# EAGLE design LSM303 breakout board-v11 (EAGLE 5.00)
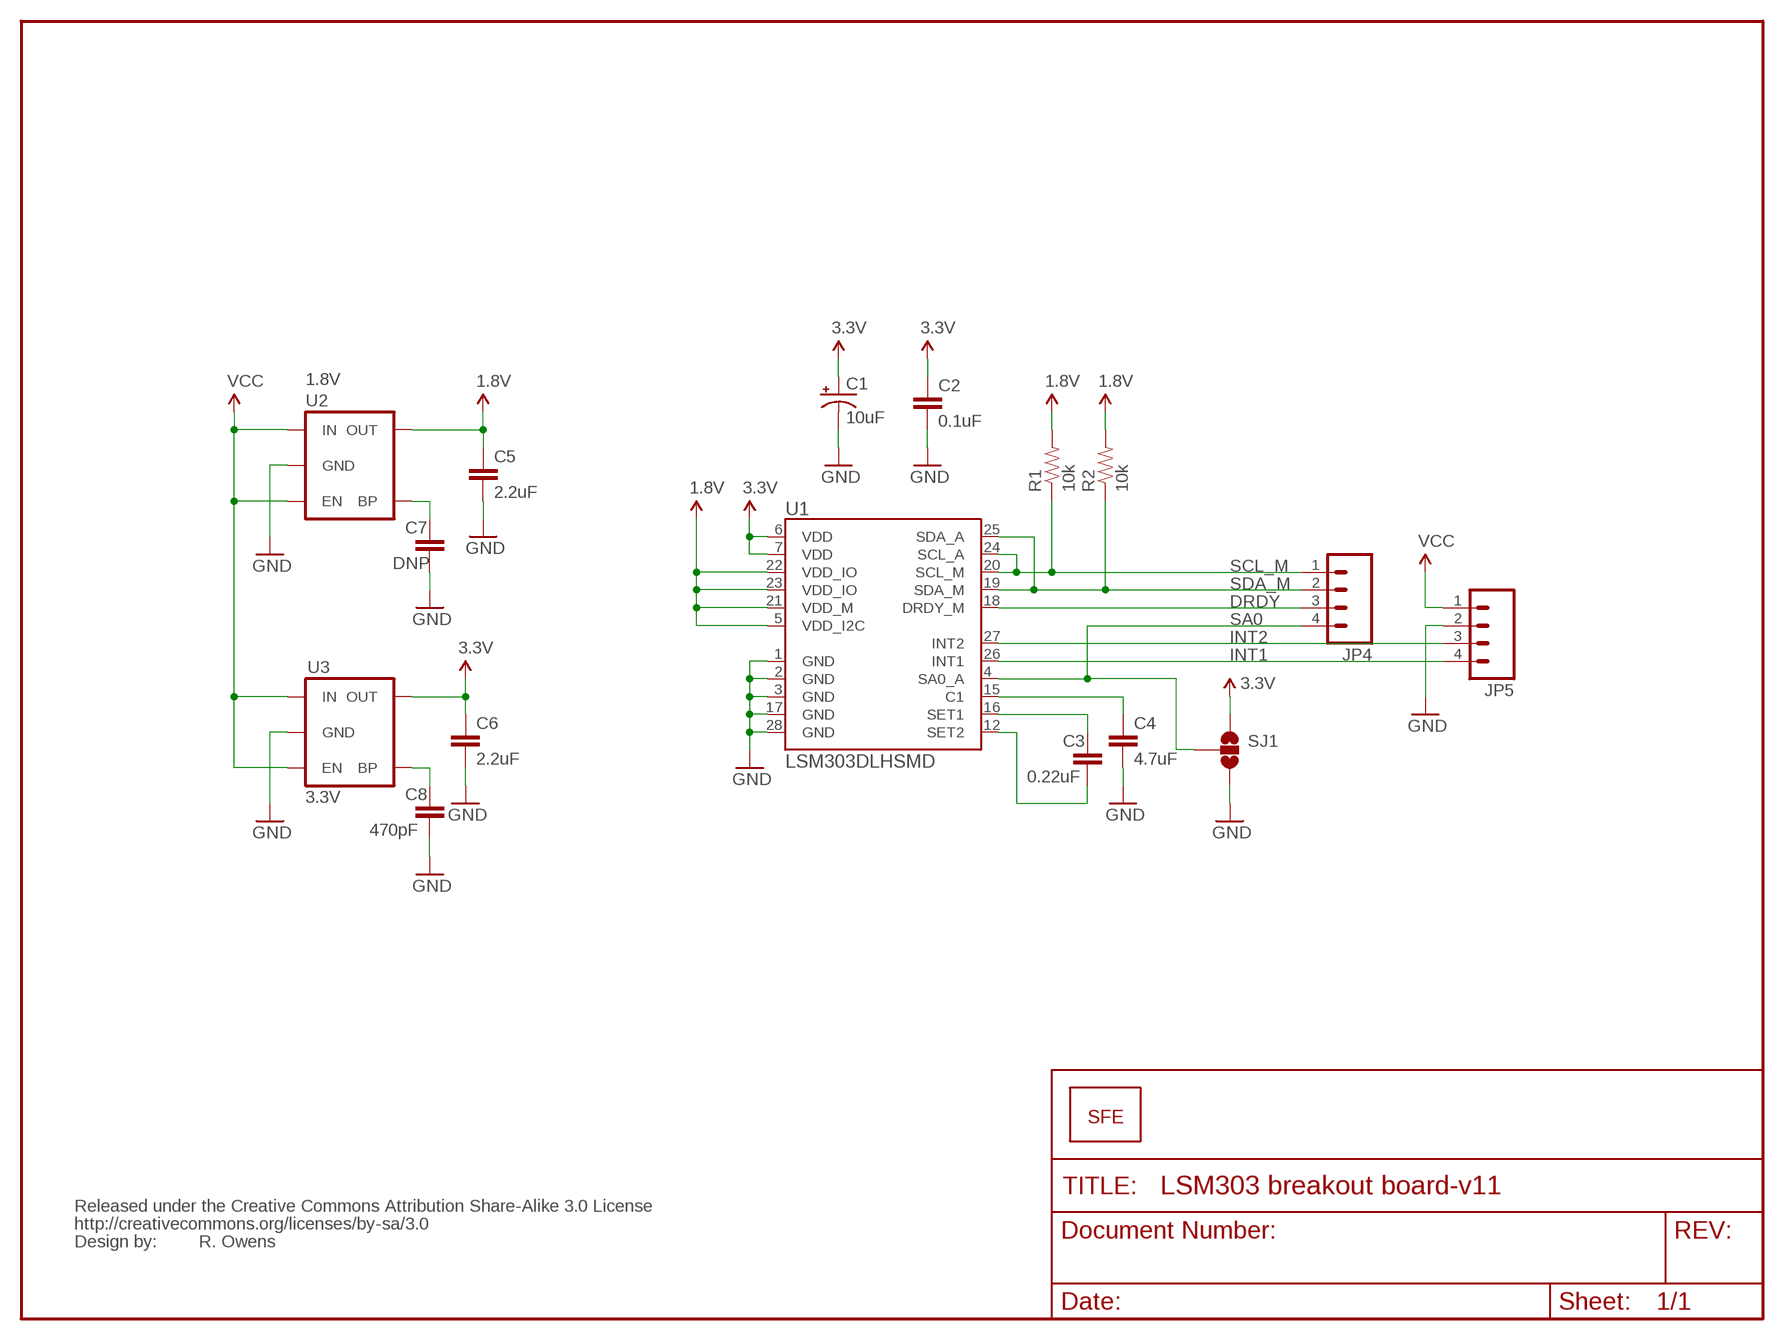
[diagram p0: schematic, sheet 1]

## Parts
C1  10uF  CAP_POL1206  [EIA3216]
C2  0.1uF  CAP0603-CAP  [0603-CAP]
C3  0.22uF  CAP0603-CAP  [0603-CAP]
C4  4.7uF  CAP0603-CAP  [0603-CAP]
C5  2.2uF  CAP0603-CAP  [0603-CAP]
C6  2.2uF  CAP0603-CAP  [0603-CAP]
C7  DNP  CAP0603-CAP  [0603-CAP]
C8  470pF  CAP0603-CAP  [0603-CAP]
JP1  LOGO-SFENEW  [SFE-NEW-WEBLOGO]
JP4  M04PTH  [1X04]
JP5  M04PTH  [1X04]
R1  10k  RESISTOR0603-RES  [0603-RES]
R2  10k  RESISTOR0603-RES  [0603-RES]
SJ1  SOLDERJUMPER_2WAYPASTE2&3  [SJ_3_PASTE2&3]
U1  LSM303DLHSMD  [LGA28-5X5]
U2  1.8V  V_REG_LDOSMD2  [SC70]
U3  3.3V  V_REG_LDOSMD  [SOT23-5]
U$5  CREATIVE_COMMONS  [CREATIVE_COMMONS]

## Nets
1.8V: C5.1 R1.2 R2.2 U1.5(VDD_I2C) U1.21(VDD_M) U1.22(VDD_IO) U1.23(VDD_IO) U2.5(OUT)
3.3V: C1.A(+) C2.1 C6.1 SJ1.1 U1.6(VDD) U1.7(VDD) U3.5(OUT)
DRDY: JP4.3 U1.18(DRDY_M)
GND: C1.C(-) C2.2 C4.2 C5.2 C6.2 C7.2 C8.2 JP5.2 SJ1.3 U1.1(GND) U1.2(GND) U1.3(GND) U1.17(GND) U1.28(GND) U2.2(GND) U3.2(GND)
INT1: JP5.4 U1.26(INT1)
INT2: JP5.3 U1.27(INT2)
N$6: C7.1 U2.4(BP)
N$7: C8.1 U3.4(BP)
N$10: C3.1 U1.16(SET1)
N$11: C3.2 U1.12(SET2)
N$12: C4.1 U1.15(C1)
SA0: JP4.4 SJ1.2 U1.4(SA0_A)
SCL_M: JP4.1 R1.1 U1.20(SCL_M) U1.24(SCL_A)
SDA_M: JP4.2 R2.1 U1.19(SDA_M) U1.25(SDA_A)
VCC: JP5.1 U2.1(IN) U2.3(EN) U3.1(IN) U3.3(EN)

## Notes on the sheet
- R. Owens

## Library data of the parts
C1 = SparkFun:CAP_POL: Capacitor Polarized
C2-C8 = SparkFun:CAP: Capacitor
JP1 = SparkFun:LOGO-SFE: Spark Fun Electronics PCB Logo
JP4 JP5 = SparkFun:M04: Header 4 Standard 4-pin 0.1" header. Use with straight break away headers (SKU : PRT-00116), right angle break away headers (PRT-00553), swiss pins (PRT-00743), machine pins (PRT-00117), and female headers (PRT-00115). Molex polarized connector foot print use with SKU : PRT-08231 with associated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
R1 R2 = SparkFun:RESISTOR: Resistor
SJ1 = SparkFun:SOLDERJUMPER_2WAY: Solder Jumper 2 way solder jumper
U1 = SparkFun:LSM303DLH
U2 U3 = SparkFun:V_REG_LDO: Voltage Regulator LDO Standard 150mA LDO voltage regulator in SOT-23 layout. Micrel part MIC5205. BP (by-pass) pin is used to lower output noise with 470pF cap.
U$5 = SparkFun:CREATIVE_COMMONS

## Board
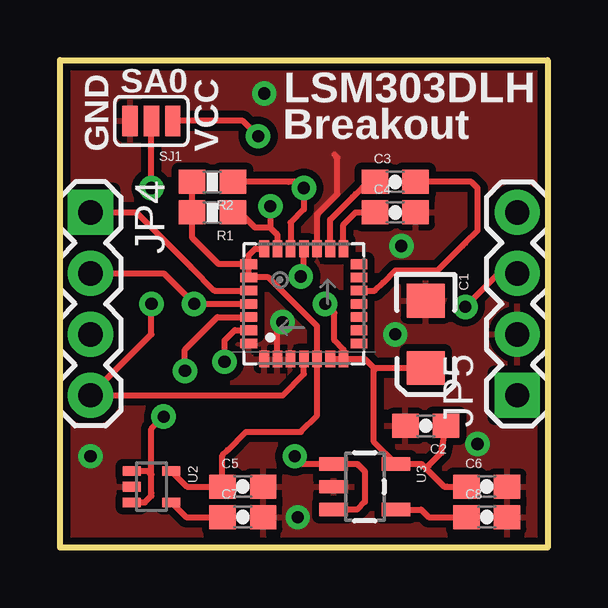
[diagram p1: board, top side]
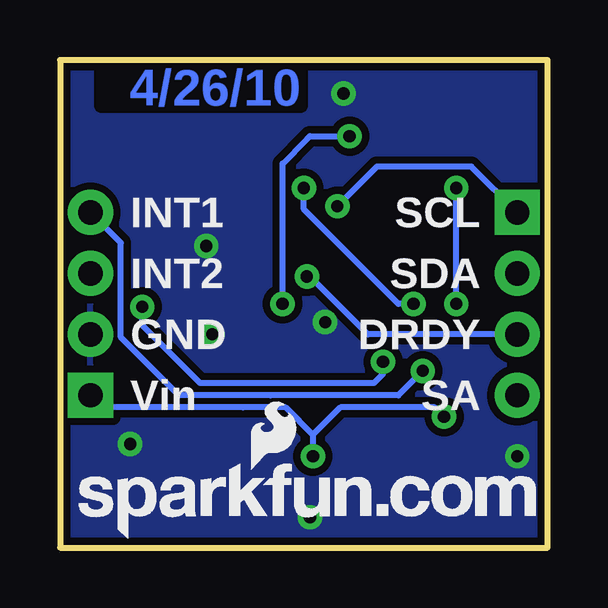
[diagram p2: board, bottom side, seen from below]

Size 20.32 x 20.32 mm. Coordinates in mm from the lower left corner, seen from the top.
Outline: 0,0 0,20.32 20.32,20.32 20.32,0 0,0
Copper layers (1*16): Top 0.035mm / dielectric 1.5mm / Bottom 0.035mm
Design rules "SparkFun *": minimum track width 8mil, minimum drill 20mil, track to track 8mil, track to pad 5mil, pad to pad 5mil, via to via 8mil, smd to smd 5mil, copper to edge 8mil, drill to drill 8mil, minimum pad ring 12mil, minimum via ring 10mil, stop-mask expansion 4mil, vias tented up to drill 20mil, thermal gap 10mil

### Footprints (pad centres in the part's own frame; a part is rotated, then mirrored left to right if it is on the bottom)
EIA3216 = smd 1.4 x 1.6: A 1.4,0; C -1.4,0
0603-CAP = smd 1.1 x 1: 1 -0.85,0; 2 0.85,0
1X04 = drill 1.016 pad 1.88 square: 1 0,0 | drill 1.016 pad 1.88 round: 2 2.54,0; 3 5.08,0; 4 7.62,0
0603-RES = smd 1.1 x 1: 1 -0.85,0; 2 0.85,0
SJ_3_PASTE2&3 = smd 0.635 x 1.27: 1 -0.889,0; 2 0,0; 3 0.889,0
LGA28-5X5 = smd 0.7 x 0.4: 1 -2.3,1.65; 2 -2.3,1.1; 3 -2.3,0.55; 4 -2.3,0; 5 -2.3,-0.55; 6 -2.3,-1.1; 7 -2.3,-1.65; 15 2.3,-1.65; 16 2.3,-1.1; 17 2.3,-0.55; 18 2.3,0; 19 2.3,0.55; 20 2.3,1.1; 21 2.3,1.65 | smd 0.4 x 0.7: 8 -1.65,-2.3; 9 -1.1,-2.3; 10 -0.55,-2.3; 11 0,-2.3; 12 0.55,-2.3; 13 1.1,-2.3; 14 1.65,-2.3; 22 1.65,2.3; 23 1.1,2.3; 24 0.55,2.3; 25 0,2.3; 26 -0.55,2.3; 27 -1.1,2.3; 28 -1.65,2.3
SC70 = smd 0.4 x 0.75: 1 -0.65,-0.825; 2 0,-0.825; 3 0.65,-0.825; 4 0.65,0.825; 5 -0.65,0.825
SOT23-5 = smd 0.55 x 1.2: 1 -0.95,-1.3; 2 0,-1.3; 3 0.95,-1.3; 4 0.95,1.3; 5 -0.95,1.3

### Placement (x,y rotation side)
C1  15.24,8.89 270 top
C2  15.24,5.08 180 top
C3  13.97,15.24 0 top
C4  13.97,13.97 0 top
C5  7.62,2.54 0 top
C6  17.78,2.54 0 top
C7  7.62,1.27 0 top
C8  17.78,1.27 0 top
JP1  19.56,0.38 0 bottom
JP4  1.27,13.97 270 top
JP5  19.05,6.35 90 top
R1  6.35,13.97 180 top
R2  6.35,15.24 180 top
SJ1  3.81,17.78 180 top
U1  10.16,10.16 90 top
U2  3.81,2.54 270 top
U3  12.7,2.54 270 top
U$5  not placed on the board

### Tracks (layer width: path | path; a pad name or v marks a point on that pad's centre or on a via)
1.8V
  Top 0.254: C5.1 6.86,2.54 C5.1 | U2.5 5.29,2.54 C5.1 | U1.22 7.87,11.81 7.86,11.8 U1.23 8.68,11.26 10.67,9.27 10.71,9.23 10.71,8.97 U1.5 10.71,5.5 10.03,4.83 7.75,4.83 6.99,4.06 6.77,3.85 C5.1 | U1.22 6.61,11.81 5.59,12.83 5.5,12.91 R1.2 5.46,13.97 5.5,14.01 R2.2 | U1.22 7.86,12.18 7.87,12.19 8.14,12.46 U1.21
3.3V  (via drill 0.51)
  Top 0.254: U1.7 11.7,7.86 11.68,7.87 11.67,7.86 U1.6 | U1.7 12.71,7.86 13.08,7.49 | 15.05,3.49 15.11,3.43 | 15.11,3.43 15.24,3.3 | 15.24,3.3 16,2.54 16.13,2.54 C6.1 | U1.7 11.81,8.26 11.43,8.64 11.43,9.78 v11.05,10.16 | SJ1.1 7.62,17.78 v8.26,17.14 | 13.08,7.49 13.08,7.37 13.08,4.41 U3.5 15.05,3.49 | 15.05,3.49 15.11,3.43 | 15.24,3.3 15.37,3.43 15.89,3.95 C2.1 | C1.A 13.08,7.49
  Bottom 0.254: v11.05,10.16 11.05,15.11 11.05,16 10.03,17.02 9.91,17.14 v8.26,17.14
DRDY  (via drill 0.51)
  Top 0.254: U1.18 10.16,11.43 v10.03,11.3
  Bottom 0.254: JP4.3 1.52,8.89 7.49,8.89 9.91,11.3 v10.03,11.3
GND  (via drill 0.51)
  Top 0.254: v9.27,9.4 9.27,9.27 9.06,9.06 U1.2 | U1.17 10.71,13.88 11.56,14.73 11.56,16.26 11.43,16.38
  other vias: 14.22,12.57 8.51,18.92 13.97,8.89 9.91,1.27 17.4,4.32 1.27,3.81
  pour Top (isolate 0.305): 0,0 0,20.32 20.32,20.32 20.32,0
  pour Bottom (isolate 0.305): 0,0 0,20.32 20.32,20.32 20.32,0
INT1  (via drill 0.51)
  Top 0.254: U1.26 6.56,9.61 5.21,8.26 v5.21,7.37
  Bottom 0.254: v5.21,7.37 6.22,6.35 11.56,6.35 15.37,6.35 17.78,8.76 17.78,12.7 JP5.4
INT2  (via drill 0.51)
  Top 0.254: U1.27 7.28,9.06 6.86,8.64 v6.86,7.75 | JP5.3 18.92,11.43 18.29,11.43 v16.89,10.03
  Bottom 0.254: v6.86,7.75 6.86,7.24 7.24,6.86 14.48,6.86 16.89,9.27 v16.89,10.03
N$6
  Top 0.254: C7.1 6.73,1.27 5.25,1.27 U2.4
N$7
  Top 0.254: U3.4 15.05,1.59 15.37,1.27 16.64,1.27 C8.1
N$10
  Top 0.254: U1.16 11.26,13.67 12.19,14.61 12.32,14.73 12.83,15.24 C3.1
N$11
  Top 0.254: U1.12 13.12,10.71 13.46,11.05 13.97,11.56 14.73,11.56 15.75,11.56 16.76,12.57 16.89,12.7 17.4,13.21 17.4,13.34 17.4,14.99 17.14,15.24 C3.2
N$12
  Top 0.254: U1.15 11.81,13.46 12.32,13.97 12.95,13.97 C4.1
SA0  (via drill 0.51)
  Top 0.254: v3.81,14.99 SJ1.2 | v3.81,10.16 3.81,8.89 JP4.4 3.05,6.35 3.3,6.35 6.73,6.35 7.11,6.35 9.27,6.35 10.16,7.24 U1.4
  Bottom 0.254: v3.81,10.16 v3.81,14.99
SCL_M  (via drill 0.51)
  Top 0.254: U1.24 6.43,10.71 5.46,11.68 3.17,13.97 2.16,13.97 1.78,13.97 JP4.1 1.4,13.97 | R1.1 7.49,13.97 8.13,13.34 8.76,13.34 | 8.76,13.34 9.02,13.08 9.06,13.04 U1.20 | v8.76,14.22 8.76,13.34
  Bottom 0.254: JP4.1 3.17,15.88 4.83,15.88 7.11,15.88 v8.76,14.22
SDA_M  (via drill 0.51)
  Top 0.254: U1.25 5.97,10.16 v5.59,10.16 4.32,11.43 3.81,11.43 3.68,11.43 1.52,11.43 JP4.2 | U1.19 9.61,13.55 10.16,14.1 10.16,14.86 v10.16,14.99 9.91,15.24 9.53,15.24 R2.1
  Bottom 0.254: v10.16,14.99 10.16,14.1 8.89,12.83 7.49,11.43 6.22,10.16 v5.59,10.16
VCC  (via drill 0.51)
  Top 0.254: U2.3 3.54,1.89 3.81,2.16 3.81,2.29 3.81,3.05 | 12.45,3.43 12.7,3.17 12.7,2.92 12.7,1.91 12.38,1.59 U3.3 | 12.38,3.49 12.45,3.43 | 3.81,3.05 3.81,4.95 v4.32,5.46 | U2.1 3.67,3.19 3.81,3.05 | v9.78,3.81 10.1,3.49 U3.1 12.38,3.49 | 12.38,3.49 12.45,3.43
  Bottom 0.254: v4.32,5.46 4.7,5.84 8.64,5.84 9.78,4.7 | JP5.1 18.54,5.84 12.7,5.84 10.92,5.84 9.78,4.7 | v9.78,3.81 9.78,4.45 9.78,4.57 9.78,4.7

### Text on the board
Bottom: 4/26/10
tPlace: LSM303DLH | SA0 | GND | VCC | Breakout
bPlace: SCL | INT1 | SDA | INT2 | DRDY | GND | SA | Vin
